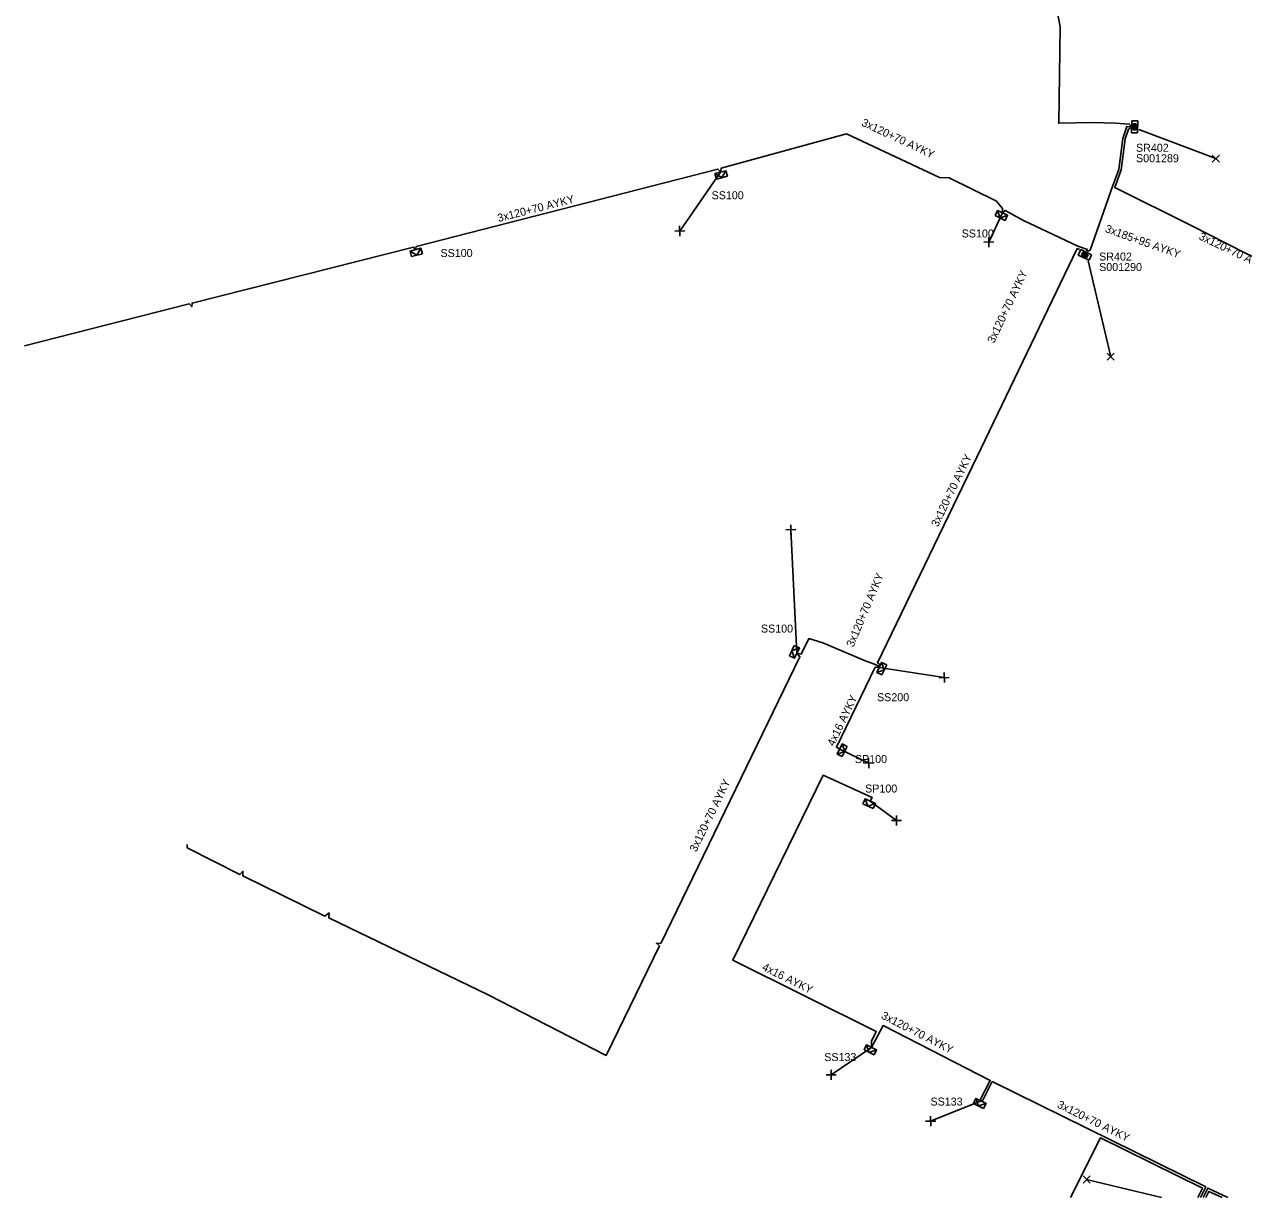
# Model space of a CAD drawing. Extents: x -762500 to -761285, y -1155006 to -1154135.
# Drawn here: x -762359.2 to -762207.7, y -1155000 to -1154854.2 of the extents above; entities that cross this region are included whole.
import ezdxf

# ---------------------------------------------------------------- set-up
doc = ezdxf.new("R2010")
doc.units = 0
for name, color, linetype in [('Vrstva 28', 7, 'Continuous'), ('Vrstva 29', 7, 'Continuous'), ('Vrstva 30', 7, 'Continuous'), ('Vrstva 31', 7, 'Continuous'), ('Vrstva 33', 7, 'Continuous'), ('Vrstva 34', 7, 'Continuous'), ('Vrstva 5', 7, 'Continuous'), ('Vrstva 59', 7, 'Continuous'), ('Vrstva 6', 7, 'Continuous')]:
    doc.layers.add(name, color=color, linetype=linetype)

msp = doc.modelspace()

# ---------------------------------------------------------------- linework, layer by layer
at = {"layer": 'Vrstva 28'}
for points in [[(-762221.63, -1154866.178), (-762221.656, -1154867.678)], [(-762220.88, -1154866.191), (-762221.63, -1154866.178)], [(-762221.454, -1154866.565), (-762221.467, -1154867.309)], [(-762221.467, -1154867.309), (-762221.089, -1154867.315)], [(-762221.076, -1154866.571), (-762221.454, -1154866.565)], [(-762221.407, -1154866.613), (-762221.419, -1154867.262)], [(-762221.419, -1154867.262), (-762221.135, -1154867.267)], [(-762221.124, -1154866.618), (-762221.407, -1154866.613)], [(-762221.361, -1154866.661), (-762221.371, -1154867.216)], [(-762221.371, -1154867.216), (-762221.182, -1154867.219)], [(-762221.172, -1154866.664), (-762221.361, -1154866.661)], [(-762221.315, -1154866.709), (-762221.323, -1154867.17)], [(-762221.323, -1154867.17), (-762221.228, -1154867.171)], [(-762221.22, -1154866.711), (-762221.315, -1154866.709)], [(-762221.275, -1154867.129), (-762221.268, -1154866.751)], [(-762221.228, -1154867.171), (-762221.22, -1154866.711)], [(-762221.182, -1154867.219), (-762221.172, -1154866.664)], [(-762221.135, -1154867.267), (-762221.124, -1154866.618)], [(-762221.089, -1154867.315), (-762221.076, -1154866.571)], [(-762220.906, -1154867.691), (-762220.88, -1154866.191)], [(-762221.656, -1154867.678), (-762220.906, -1154867.691)], [(-762227.986, -1154882.191), (-762228.303, -1154882.87)], [(-762226.626, -1154882.825), (-762227.986, -1154882.191)], [(-762227.726, -1154882.514), (-762227.886, -1154882.856)], [(-762227.703, -1154882.577), (-762227.823, -1154882.834)], [(-762227.68, -1154882.639), (-762227.76, -1154882.811)], [(-762227.052, -1154882.828), (-762227.726, -1154882.514)], [(-762227.114, -1154882.851), (-762227.703, -1154882.577)], [(-762227.658, -1154882.702), (-762227.697, -1154882.788)], [(-762227.177, -1154882.874), (-762227.68, -1154882.639)], [(-762227.24, -1154882.897), (-762227.658, -1154882.702)], [(-762228.303, -1154882.87), (-762226.943, -1154883.504)], [(-762227.886, -1154882.856), (-762227.211, -1154883.171)], [(-762227.823, -1154882.834), (-762227.234, -1154883.108)], [(-762227.76, -1154882.811), (-762227.257, -1154883.045)], [(-762227.697, -1154882.788), (-762227.28, -1154882.983)], [(-762227.64, -1154882.763), (-762227.297, -1154882.922)], [(-762227.28, -1154882.983), (-762227.24, -1154882.897)], [(-762227.257, -1154883.045), (-762227.177, -1154882.874)], [(-762227.234, -1154883.108), (-762227.114, -1154882.851)], [(-762227.211, -1154883.171), (-762227.052, -1154882.828)], [(-762226.943, -1154883.504), (-762226.626, -1154882.825)]]:
    msp.add_lwpolyline(points, dxfattribs=at)
at = {"layer": 'Vrstva 31'}
for points in [[(-762273.248, -1154873.418), (-762273.429, -1154872.742), (-762272.077, -1154872.38), (-762271.895, -1154873.056)], [(-762272.572, -1154873.237), (-762273.429, -1154872.742)], [(-762273.248, -1154873.418), (-762271.895, -1154873.056)], [(-762272.572, -1154873.237), (-762272.077, -1154872.38)], [(-762238.623, -1154877.968), (-762238.328, -1154877.333), (-762237.059, -1154877.925), (-762237.355, -1154878.559)], [(-762238.623, -1154877.968), (-762237.355, -1154878.559)], [(-762237.989, -1154878.264), (-762238.328, -1154877.333)], [(-762237.989, -1154878.264), (-762237.059, -1154877.925)], [(-762311.138, -1154883.058), (-762311.319, -1154882.382), (-762309.967, -1154882.02), (-762309.786, -1154882.696)], [(-762310.462, -1154882.877), (-762311.319, -1154882.382)], [(-762311.138, -1154883.058), (-762309.786, -1154882.696)], [(-762310.462, -1154882.877), (-762309.967, -1154882.02)], [(-762263.578, -1154931.397), (-762264.17, -1154932.666)], [(-762263.578, -1154931.397), (-762262.944, -1154931.693), (-762263.535, -1154932.962), (-762264.17, -1154932.666)], [(-762263.874, -1154932.032), (-762262.944, -1154931.693)], [(-762263.874, -1154932.032), (-762263.535, -1154932.962)], [(-762252.682, -1154935.053), (-762253.317, -1154934.757), (-762252.725, -1154933.488), (-762252.091, -1154933.784)], [(-762252.386, -1154934.419), (-762252.725, -1154933.488)], [(-762252.682, -1154935.053), (-762252.091, -1154933.784)], [(-762252.386, -1154934.419), (-762253.317, -1154934.757)], [(-762257.609, -1154945.189), (-762258.238, -1154944.882), (-762257.624, -1154943.624), (-762256.995, -1154943.93)], [(-762257.302, -1154944.56), (-762258.238, -1154944.882)], [(-762257.302, -1154944.56), (-762257.624, -1154943.624)], [(-762257.609, -1154945.189), (-762256.995, -1154943.93)], [(-762255.067, -1154951.074), (-762254.782, -1154950.435), (-762253.503, -1154951.004), (-762253.788, -1154951.644)], [(-762254.427, -1154951.359), (-762254.782, -1154950.435)], [(-762255.067, -1154951.074), (-762253.788, -1154951.644)], [(-762254.427, -1154951.359), (-762253.503, -1154951.004)], [(-762254.908, -1154981.651), (-762254.602, -1154981.022), (-762253.343, -1154981.636), (-762253.65, -1154982.265)], [(-762254.279, -1154981.958), (-762254.602, -1154981.022)], [(-762254.908, -1154981.651), (-762253.65, -1154982.265)], [(-762254.279, -1154981.958), (-762253.343, -1154981.636)], [(-762241.309, -1154988.302), (-762241.002, -1154987.672), (-762239.743, -1154988.286), (-762240.05, -1154988.915)], [(-762241.309, -1154988.302), (-762240.05, -1154988.915)], [(-762240.679, -1154988.609), (-762241.002, -1154987.672)], [(-762240.679, -1154988.609), (-762239.743, -1154988.286)]]:
    msp.add_lwpolyline(points, dxfattribs=at)
at = {"layer": 'Vrstva 34'}
for points in [[(-762211.632, -1154870.438), (-762210.748, -1154871.322)], [(-762211.632, -1154871.322), (-762210.748, -1154870.438)], [(-762277.799, -1154880.505), (-762277.821, -1154879.255)], [(-762278.435, -1154879.891), (-762277.185, -1154879.869)], [(-762239.389, -1154881.875), (-762239.411, -1154880.625)], [(-762240.025, -1154881.261), (-762238.775, -1154881.239)], [(-762224.692, -1154895.058), (-762223.808, -1154895.942)], [(-762224.692, -1154895.942), (-762223.808, -1154895.058)], [(-762264.625, -1154917.011), (-762263.375, -1154916.989)], [(-762263.989, -1154917.625), (-762264.011, -1154916.375)], [(-762245.565, -1154935.391), (-762244.315, -1154935.369)], [(-762244.929, -1154936.005), (-762244.951, -1154934.755)], [(-762254.955, -1154946.011), (-762253.705, -1154945.989)], [(-762254.319, -1154946.625), (-762254.341, -1154945.375)], [(-762251.505, -1154953.141), (-762250.255, -1154953.119)], [(-762250.869, -1154953.755), (-762250.891, -1154952.505)], [(-762258.989, -1154985.375), (-762259.011, -1154984.125)], [(-762259.625, -1154984.761), (-762258.375, -1154984.739)], [(-762246.619, -1154991.125), (-762246.641, -1154989.875)], [(-762247.255, -1154990.511), (-762246.005, -1154990.489)], [(-762227.692, -1154997.308), (-762226.808, -1154998.192)], [(-762227.692, -1154998.192), (-762226.808, -1154997.308)]]:
    msp.add_lwpolyline(points, dxfattribs=at)
at = {"layer": 'Vrstva 5'}
for points in [[(-762244.34, -1154807.48), (-762244.06, -1154807.51), (-762242.57, -1154811.69), (-762240.66, -1154817.36), (-762238.6, -1154821.07), (-762233.72, -1154840.05), (-762232.04, -1154846.62), (-762230.54, -1154854.49), (-762230.71, -1154866.48), (-762226.47, -1154866.4), (-762223.66, -1154866.46), (-762221.96, -1154866.6), (-762221.77, -1154866.8)], [(-762221.77, -1154866.93), (-762222.27, -1154866.91), (-762222.73, -1154868.38), (-762223.23, -1154872.22), (-762223.97, -1154874.24), (-762226.82, -1154882.26), (-762227.2, -1154882.42)], [(-762221.78, -1154867.06), (-762222.05, -1154867.23), (-762222.44, -1154868.44), (-762222.94, -1154872.29), (-762223.69, -1154874.34), (-762223.76, -1154874.47), (-762214.19, -1154879.24), (-762207.57, -1154882.59), (-762187.13, -1154892.38), (-762186.62, -1154892.07)], [(-762359.25, -1154894.16), (-762338.76, -1154888.92), (-762338.46, -1154889.26), (-762338.41, -1154888.83), (-762310.89, -1154881.88), (-762310.64, -1154882.2), (-762310.56, -1154881.79), (-762273.09, -1154872.18), (-762272.75, -1154872.56), (-762272.68, -1154872.07), (-762257.1, -1154867.81), (-762245.54, -1154873.23), (-762244.31, -1154873.27), (-762238.44, -1154876.17), (-762237.69, -1154877.08), (-762237.69, -1154877.63), (-762237.38, -1154877.32), (-762235.08, -1154878.58), (-762228.32, -1154881.78), (-762227.14, -1154882.16), (-762227.31, -1154882.36)], [(-762253.02, -1154934.12), (-762252.98, -1154933.71), (-762253.24, -1154933.54), (-762240.9, -1154908), (-762228.41, -1154882.07), (-762228.12, -1154882.16)], [(-762339.01, -1154956.12), (-762339.01, -1154956.52), (-762332.46, -1154959.85), (-762332.1, -1154959.44), (-762332.11, -1154960.01), (-762321.9, -1154965.01), (-762321.38, -1154964.63), (-762321.4, -1154965.25), (-762301.62, -1154974.8), (-762286.97, -1154982.32), (-762280.33, -1154968.72), (-762280.71, -1154968.39), (-762280.17, -1154968.4), (-762262.87, -1154932.81), (-762263.24, -1154932.33), (-762262.71, -1154932.46), (-762261.78, -1154930.53), (-762260.03, -1154931.06), (-762254.84, -1154933.25), (-762253.4, -1154933.8), (-762253.12, -1154933.99), (-762253.02, -1154934.12)], [(-762253.02, -1154934.12), (-762253.54, -1154934.07), (-762258.33, -1154944.03), (-762257.93, -1154944.25)], [(-762253.97, -1154981.33), (-762253.99, -1154980.54), (-762253.39, -1154979.37), (-762271.22, -1154970.51), (-762260, -1154947.51), (-762253.91, -1154950.26), (-762254.14, -1154950.72)], [(-762213.09, -1155000), (-762212.45, -1154998.68), (-762238.98, -1154985.58), (-762240.19, -1154987.96), (-762240.37, -1154987.98), (-762240.44, -1154987.77), (-762239.23, -1154985.44), (-762252.55, -1154978.63), (-762253.97, -1154981.33)], [(-762229.25, -1155000), (-762225.54, -1154992.55), (-762212.85, -1154998.82), (-762213.42, -1155000)], [(-762212.76, -1155000), (-762212.18, -1154998.82), (-762209.7, -1155000)], [(-762210.4, -1155000), (-762212.04, -1154999.22), (-762212.42, -1155000)]]:
    msp.add_lwpolyline(points, dxfattribs=at)
at = {"layer": 'Vrstva 59'}
for points in [[(-762220.77, -1154867.26), (-762211.19, -1154870.88)], [(-762272.75, -1154872.56), (-762277.81, -1154879.88)], [(-762237.69, -1154877.63), (-762239.4, -1154881.25)], [(-762227.05, -1154883.6), (-762224.25, -1154895.5)], [(-762263.24, -1154932.33), (-762264, -1154917)], [(-762253.02, -1154934.12), (-762244.94, -1154935.38)], [(-762257.93, -1154944.25), (-762254.33, -1154946)], [(-762254.14, -1154950.72), (-762250.88, -1154953.13)], [(-762253.97, -1154981.33), (-762259, -1154984.75)], [(-762240.37, -1154987.98), (-762246.63, -1154990.5)], [(-762217.95, -1155000), (-762227.25, -1154997.75)]]:
    msp.add_lwpolyline(points, dxfattribs=at)

# ---------------------------------------------------------------- texts
at = {"layer": 'Vrstva 29'}
for s, p in [('S001289', (-762221.11, -1154871.33)), ('S001290', (-762225.69, -1154884.85))]:
    msp.add_text(s, height=0.9943, dxfattribs=at).set_placement(p)
at = {"layer": 'Vrstva 30'}
for p in [(-762221.11, -1154870.03), (-762225.69, -1154883.55)]:
    msp.add_text('SR402', height=0.9943, dxfattribs=at).set_placement(p)
at = {"layer": 'Vrstva 33'}
for s, p in [('SS100', (-762273.85, -1154875.93)), ('SS100', (-762242.77, -1154880.68)), ('SS100', (-762307.54, -1154883.11)), ('SS100', (-762267.72, -1154929.78)), ('SS200', (-762253.29, -1154938.31)), ('SP100', (-762256.04, -1154946)), ('SP100', (-762254.77, -1154949.66)), ('SS133', (-762259.85, -1154983.03)), ('SS133', (-762246.65, -1154988.56))]:
    msp.add_text(s, height=0.9943, dxfattribs=at).set_placement(p)
at = {"layer": 'Vrstva 6'}
for s, height, rotation, p in [('3x120+70 AYKY', 0.99429, 334.88009, (-762255.32, -1154866.74)), ('3x120+70 AYKY', 0.99429, 14.39614, (-762300.32, -1154878.77)), ('3x185+95 AYKY', 0.99428, 340.45618, (-762225.03, -1154879.99)), ('3x120+70 AYKY', 0.99429, 334.42456, (-762213.39, -1154880.87)), ('3x120+70 AYKY', 0.99429, 64.6684, (-762238.75, -1154893.91)), ('3x120+70 AYKY', 0.99429, 64.20502, (-762245.73, -1154916.74)), ('3x120+70 AYKY', 0.99428, 67.12194, (-762256.24, -1154931.67)), ('4x16 AYKY', 0.9943, 64.33244, (-762258.65, -1154943.98)), ('3x120+70 AYKY', 0.99429, 64.07731, (-762275.76, -1154957.13)), ('4x16 AYKY', 0.9943, 333.5572, (-762267.67, -1154971.67)), ('3x120+70 AYKY', 0.99429, 332.92284, (-762252.86, -1154977.69)), ('3x120+70 AYKY', 0.99429, 333.71553, (-762230.99, -1154988.76))]:
    msp.add_text(s, height=height, rotation=rotation, dxfattribs=at).set_placement(p)

doc.saveas('drawing.dxf')
